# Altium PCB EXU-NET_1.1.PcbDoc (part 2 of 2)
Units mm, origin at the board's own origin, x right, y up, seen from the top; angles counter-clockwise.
Board outline 89 x 74.45 mm, 4 copper layers (Top Layer, Layer 1, Layer 2, Bottom Layer), stack 1.57 mm thick; 116 components, 84 nets, 406 pads, 488 vias.
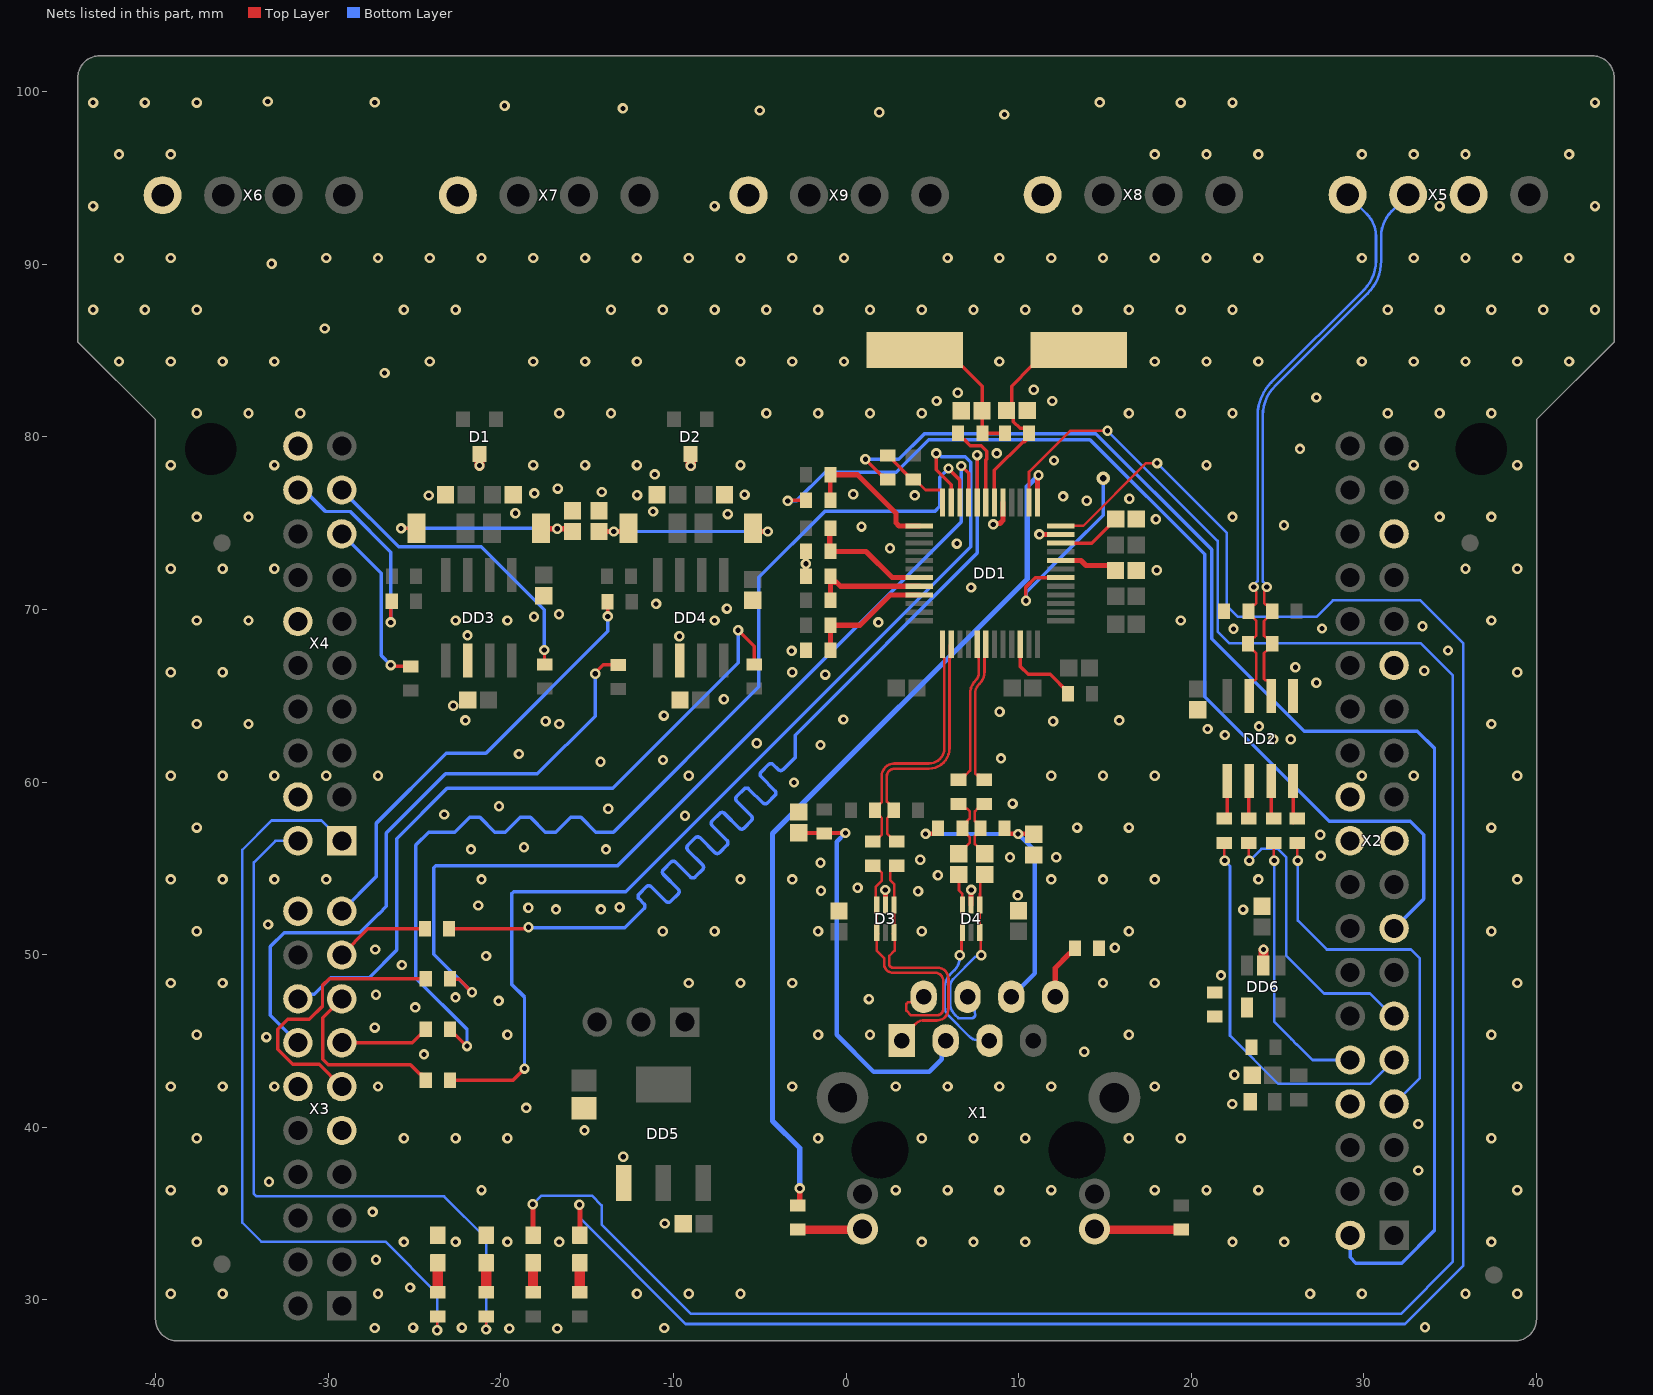
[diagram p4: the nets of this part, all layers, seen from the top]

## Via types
v1: diameter 0.6, hole 0.3, Top Layer to Bottom Layer, tented both sides, 487 vias
v2: diameter 0.8, hole 0.4, Top Layer to Bottom Layer, tented bottom, 1 vias

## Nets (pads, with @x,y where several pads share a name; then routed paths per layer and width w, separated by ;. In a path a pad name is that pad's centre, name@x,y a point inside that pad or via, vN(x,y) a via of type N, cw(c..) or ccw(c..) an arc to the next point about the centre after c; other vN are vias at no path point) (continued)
GND: C2.2 C3.2 C5.2 C6.2 C13.1 C14.1 C15.1 C16.1 C17.1 C18.2 C19.2 C20.2 C21.1 C22.1 C23.2 C24.2 C25.2 C26.1 C27.1 C28.1 C29.1 C30.2 C31.2 D1.3 D2.3 D3.2 D4.2 DD1.23 DD1.29 DD2.5 DD3.2 DD4.2 DD5.1 DD6.2 L1.2 R18.1 R20.1 R22.1 R32.1 R35.1 R54.2 VD3.2 VD4.2 X2.8 X2.19 X2.20 X2.22 X2.27 X2.33 X3.9 X3.12 X3.20 X4.4 X4.12 X4.20 X5.3 X6.1 X7.1 X8.1 X9.1 | length 7.1
  Top Layer w0.3: v1(2.27,53.745) 2.281,53.734 D3.2@2.281,52.887 ; D4.2@7.245,52.887 7.245,53.743 v1(7.259,53.757) ; v1(8.53,74.929) 8.587,74.986 8.913,74.986 9.099,75.172 DD1.29@9.099,76.193 ; v1(11.2,74.35) 11.207,74.343 DD1.23@12.449,74.343
  Top Layer w0.6: D1.3@-21.247,79.023 D1.3@-21.229,79.006 v1(-21.229,78.332) ; D2.3@-9.015,79.006 -8.997,78.989 v1(-8.997,78.315) ; C13.1@16.819,75.236 C13.1@16.863,75.281 ; DD6.2@24.172,49.383 24.185,49.395 v1(24.185,50.3)
  other v1: -19.5,28.35 -16.725,28.35 -27.3,28.375 -10.525,28.375 -25.075,28.4 -22.25,28.4 33.543,28.415 -39.113,30.363 -36.113,30.363 -27.113,30.363 -12.113,30.363 -9.113,30.363 -6.113,30.363 26.887,30.363 29.887,30.363 35.887,30.363 38.887,30.363 -25.25,30.725 -27.225,32.325 -37.613,33.363 -25.613,33.363 -22.613,33.363 -19.613,33.363 -16.613,33.363 4.387,33.363 7.387,33.363 10.387,33.363 22.387,33.363 25.387,33.363 37.387,33.363 -10.5,34.425 -27.425,35.1 -39.113,36.363 -36.113,36.363 -21.113,36.363 2.887,36.363 5.887,36.363 8.887,36.363 11.887,36.363 17.887,36.363 20.887,36.363 23.887,36.363 38.887,36.363 -33.425,36.85 33.15,37.5 -12.9,38.3 -37.613,39.363 -25.613,39.363 -22.613,39.363 -19.613,39.363 -1.613,39.363 4.387,39.363 7.387,39.363 10.387,39.363 16.387,39.363 19.387,39.363 37.387,39.363 -15.15,39.825 33.153,40.193 -18.525,41.125 22.375,41.35 -39.113,42.363 -36.113,42.363 -33.113,42.363 -27.113,42.363 -3.113,42.363 2.887,42.363 5.887,42.363 8.887,42.363 11.887,42.363 17.887,42.363 38.887,42.363 22.5,43.05 -24.45,44.225 13.8,44.375 -33.575,45.225 -37.613,45.363 -19.613,45.363 -1.613,45.363 1.387,45.363 16.387,45.363 37.387,45.363 -27.3,45.775 -24.95,46.95 -20.125,47.325 1.325,47.425 -22.625,47.525 -27.225,47.675 -39.113,48.363 -36.113,48.363 -9.113,48.363 -6.113,48.363 -3.113,48.363 14.887,48.363 17.887,48.363 38.887,48.363 21.721,48.8 -25.727,49.401 -20.85,49.925 -27.275,50.3 15.578,50.4 -37.613,51.363 -10.613,51.363 -7.613,51.363 -1.613,51.363 4.387,51.363 16.387,51.363 37.387,51.363 -33.475,51.75 23.006,52.612 -16.8,52.625 -14.2,52.625 -18.4,52.725 -13.112,52.759 -21.3,52.85 9.95,53.435 4.175,53.675 -1.45,53.7 0.675,53.875 -39.113,54.363 -36.113,54.363 -33.113,54.363 -30.113,54.363 -21.113,54.363 -6.113,54.363 -3.113,54.363 11.887,54.363 14.887,54.363 17.887,54.363 23.887,54.363 38.887,54.363 5.325,54.6 -1.475,55.325 4.3,55.5 9.5,55.65 12.175,55.65 27.5,55.725 -21.725,56.1 -13.9,56.1 -18.65,56.225 27.475,56.95 -37.613,57.363 13.387,57.363 16.387,57.363 37.387,57.363 -9.325,58.05 -23.275,58.125 -13.775,58.45 -20.1,58.6 9.65,58.75 -3.016,59.972 -39.113,60.363 -36.113,60.363 -33.113,60.363 -30.113,60.363 -27.113,60.363 -9.113,60.363 11.887,60.363 14.887,60.363 17.887,60.363 29.887,60.363 32.887,60.363 38.887,60.363 -14.225,61.175 -10.6,61.275 8.975,61.375 -18.95,61.625 -1.475,62.15 -5.175,62.25 24.75,62.475 25.765,62.484 21.95,62.725 20.95,63.075 23.925,63.225 -37.613,63.363 -34.613,63.363 -16.613,63.363 37.387,63.363 -17.4,63.525 12,63.525 -22.05,63.575 15.825,63.575 -0.15,63.625 -10.55,63.85 8.9,64.075 -22.75,64.425 -7.075,64.8 27.25,65.75 -1.2,66.225 -39.113,66.363 -36.113,66.363 -3.113,66.363 38.887,66.363 33.5,66.45 26.034,66.657 -3.15,67.6 34.875,67.625 -9.65,68.45 -21.925,68.5 22.45,68.875 27.575,68.9 33.4,69.025 1.875,69.25 -37.613,69.363 -34.613,69.363 -22.613,69.363 -19.613,69.363 -7.613,69.363 19.387,69.363 37.387,69.363 -18.075,69.575 -16.625,69.725 -6.9,70.05 -11,70.325 7.25,71.275 18,72.275 -39.113,72.363 -36.113,72.363 -33.113,72.363 35.887,72.363 38.887,72.363 -2.325,72.65 2.55,73.55 6.423,73.814 0.9,74.8 25.375,74.875 17.95,75.225 -37.613,75.363 -34.613,75.363 22.387,75.363 34.387,75.363 37.387,75.363 -6.85,75.525 -19.15,75.575 -11.175,75.675 13.95,76.3 16.419,76.417 12.575,76.55 -24.175,76.6 3.985,76.606 -12.1,76.625 -5.875,76.65 0.421,76.676 -18.05,76.725 -14.15,76.8 -16.7,77 -11.075,77.825 -39.113,78.363 -33.113,78.363 -18.113,78.363 -15.113,78.363 -12.113,78.363 -6.113,78.363 20.887,78.363 32.887,78.363 38.887,78.363 12.05,78.625 8.729,79.041 26.3,79.3 -37.613,81.363 -34.613,81.363 -31.613,81.363 -16.613,81.363 -13.613,81.363 -4.613,81.363 -1.613,81.363 1.387,81.363 4.387,81.363 16.387,81.363 19.387,81.363 22.387,81.363 31.387,81.363 34.387,81.363 37.387,81.363 5.25,82.075 11.95,82.075 27.25,82.275 6.475,82.55 10.875,82.725 -26.725,83.7 -42.113,84.363 -39.113,84.363 -36.113,84.363 -33.113,84.363 -24.113,84.363 -18.113,84.363 -15.113,84.363 -12.113,84.363 -6.113,84.363 -3.113,84.363 -0.113,84.363 8.887,84.363 17.887,84.363 20.887,84.363 23.887,84.363 29.887,84.363 32.887,84.363 35.887,84.363 38.887,84.363 41.887,84.363 -30.2,86.275 -43.613,87.363 -40.613,87.363 -37.613,87.363 -25.613,87.363 -22.613,87.363 -13.613,87.363 -10.613,87.363 -7.613,87.363 -4.613,87.363 -1.613,87.363 1.387,87.363 4.387,87.363 7.387,87.363 10.387,87.363 13.387,87.363 16.387,87.363 19.387,87.363 22.387,87.363 31.387,87.363 34.387,87.363 37.387,87.363 40.387,87.363 43.387,87.363 -33.275,90.025 -42.113,90.363 -39.113,90.363 -30.113,90.363 -27.113,90.363 -24.113,90.363 -21.113,90.363 -18.113,90.363 -15.113,90.363 -12.113,90.363 -9.113,90.363 -6.113,90.363 -3.113,90.363 -0.113,90.363 5.887,90.363 8.887,90.363 11.887,90.363 14.887,90.363 17.887,90.363 20.887,90.363 23.887,90.363 29.887,90.363 32.887,90.363 35.887,90.363 38.887,90.363 41.887,90.363 -43.613,93.363 -7.613,93.363 34.387,93.363 43.387,93.363 -42.113,96.363 -39.113,96.363 17.887,96.363 20.887,96.363 23.887,96.363 29.887,96.363 32.887,96.363 35.887,96.363 41.887,96.363 9.175,98.675 1.925,98.8 -5,98.9 -12.925,99.025 -19.775,99.175 -43.613,99.363 -40.613,99.363 -37.613,99.363 -27.3,99.375 14.7,99.375 19.387,99.363 22.387,99.363 43.387,99.363 -33.5,99.425
LINKLED: DD1.25 R11.2 | length 51
  Top Layer w0.3: R11.2@-2.782,35.476 -2.675,35.583 v1(-2.675,36.466) ; DD1.25@11.099,76.193 11.099,77.724 v1(11.149,77.774)
  Bottom Layer w0.3: v1(-2.675,36.466) -2.675,38.8 -4.25,40.375 -4.25,57.019 10.499,71.768 10.499,77.124 v1(11.149,77.774)
MISO: DD1.34 R26.1 | length 63.3
  Top Layer w0.2: R26.1@-22.945,45.674 -22.945,45.574 -22.695,45.324 -22.595,45.324 -21.976,44.705 v1(-21.956,44.705) ; v1(5.935,78.162) 6.599,77.499 DD1.34@6.599,76.193
  Bottom Layer w0.2: v1(-21.956,44.705) -21.956,45.674 -24.919,48.637 -24.919,56.356 -24.177,57.098 -23.067,57.098 -22.667,57.098 -21.804,57.961 -21.204,57.961 -20.341,57.098 -19.741,57.098 -18.878,57.961 -18.278,57.961 -17.415,57.098 -16.815,57.098 -15.952,57.961 -15.352,57.961 -14.489,57.098 -13.95,57.098 -13.469,57.098 -5.05,65.517 -5.05,71.868 -1.242,75.677 5.135,75.677 5.425,75.967 5.425,77.652 v1(5.935,78.162)
MOSI: DD1.35 R27.1 | length 60.3
  Top Layer w0.2: R27.1@-22.945,42.74 -19.287,42.74 v1(-18.624,43.403) ; v1(5.23,79.042) 5.23,78.089 6.099,77.221 DD1.35@6.099,76.193
  Bottom Layer w0.2: v1(-18.624,43.403) -18.624,47.549 -19.375,48.3 -19.375,53.526 -19.258,53.643 -12.754,53.643 7.226,73.623 7.226,78.534 7.093,78.668 6.904,78.856 5.524,78.856 5.339,79.042 v1(5.23,79.042)
NetC5_1: C5.1 R13.2 R14.2 Y1.2 | length 8.9
  Top Layer w0.2: Y1.2@3.987,85.033 4.937,84.083 6.737,84.083 7.881,82.938 C5.1@7.881,81.387 ; R13.2@7.881,80.187 R13.2@7.998,80.071 ; R13.2@7.881,80.312 C5.1@7.881,81.512 ; R13.2@7.998,80.196 R14.2@9.212,80.196
NetC13_2: C13.2 DD1.22 | length 3.7
  Top Layer w0.2: DD1.22@12.449,73.843 14.225,73.843 C13.2@15.619,75.236
NetC14_2: C14.2 DD1.20 | length 3.4
  Top Layer w0.3: DD1.20@12.449,72.843 13.607,72.843 13.9,72.55 15.321,72.55 C14.2@15.617,72.254
NetC20_1: C20.1 R37.2 R38.2 | length 12
  Top Layer w0.2: v1(-25.771,74.698) -24.896,74.698 R37.2@-24.887,74.707 ; R38.2@-17.662,74.707 R38.2@-17.634,74.679 ; C20.1@-16.003,74.679 C20.1@-15.837,74.514 ; C20.1@-15.914,74.137 C20.1@-15.837,74.213
  Top Layer w0.3: R38.2@-17.634,74.679 C20.1@-16.003,74.679
  Bottom Layer w0.2: v1(-25.771,74.698) -16.747,74.698 v1(-16.728,74.679)
NetC25_1: C25.1 R40.2 R41.2 | length 11.5
  Top Layer w0.15: v1(-4.531,74.519) v1@-4.525,74.525
  Top Layer w0.3: C25.1@-14.304,74.514 v1(-13.456,74.514) -12.608,74.514 R40.2@-12.602,74.519 ; R41.2@-5.394,74.519 v1(-4.531,74.519)
  Bottom Layer w0.15: v1(-13.456,74.514) -4.531,74.514 v1(-4.531,74.519)
NetDD1_10: DD1.10 R15.2 | length 4.8
  Top Layer w0.2: DD1.10@10.104,67.988 10.104,66.693 10.557,66.24 11.834,66.24 12.861,65.213 R15.2@12.861,65.113
NetDD1_24: DD1.24 VD2.2 | length 126.1
  Top Layer w0.15: DD1.24@12.449,74.843 13.743,74.843 17.375,78.475 v1(18.025,78.475)
  Top Layer w0.3: v1(-15.443,35.517) -15.415,35.489 VD2.2@-15.415,33.75
  Bottom Layer w0.15: v1(-15.443,35.517) -15.443,34.769 -9.284,28.61 32.385,28.61 35.75,31.975 35.75,68.05 33.275,70.525 28.2,70.525 27.25,69.575 22.7,69.575 22.05,70.225 22.05,74.45 v1(18.025,78.475)
NetDD1_26: DD1.26 VD1.2 | length 130.3
  Top Layer w0.15: DD1.26@10.599,76.193 10.599,77.967 12.982,80.35 v1(15.15,80.35)
  Top Layer w0.3: v1(-18.147,35.544) -18.129,35.526 VD1.2@-18.129,33.75
  Bottom Layer w0.15: v1(-18.147,35.544) -18.129,35.544 -17.631,36.042 -14.719,36.042 -14.15,35.473 -14.15,34.363 -8.987,29.2 32.14,29.2 35.16,32.22 35.16,66.171 33.28,68.05 22.191,68.05 21.53,68.711 21.53,73.97 v1(15.15,80.35)
NetDD1_36: DD1.36 R12.1 R53.1 | length 4.8
  Top Layer w0.15: R12.1@3.905,77.517 4.005,77.517 4.604,76.918 5.524,76.918 5.599,76.843 DD1.36@5.599,76.193
  Top Layer w0.2: R53.1@2.414,78.927 2.514,78.927 2.764,78.677 2.764,78.577 3.555,77.786 3.555,77.767 3.805,77.517 R12.1@3.905,77.517
NetDD6_4: DD6.4 R31.1 R32.2
NetR9_1: R9.1 X1.10 | length 5
  Top Layer w0.5: X1.10@14.4,34.105 14.429,34.076 R9.1@19.415,34.076
NetR11_1: R11.1 X1.12 | length 3.7
  Top Layer w0.15: X1.12@0.921,34.076 X1.12@0.95,34.105
  Top Layer w0.5: R11.1@-2.782,34.076 X1.12@0.921,34.076
NetR16_2: R16.2 VD1.1 | length 1.7
  Top Layer w0.6: R16.2@-18.129,30.444 VD1.1@-18.129,32.103
NetR17_2: R17.2 VD2.1 | length 1.7
  Top Layer w0.6: R17.2@-15.415,30.444 VD2.1@-15.415,32.103
NetR29_1: R29.1 VD3.1 | length 1.7
  Top Layer w0.6: R29.1@-23.645,30.444 VD3.1@-23.645,32.103
NetR30_1: R30.1 VD4.1 | length 1.7
  Top Layer w0.6: R30.1@-20.85,30.444 VD4.1@-20.85,32.103
NetR53_2: R53.2 X2.2 | length 80.9
  Top Layer w0.2: v1(1.125,78.7) 2.048,77.777 2.164,77.777 R53.2@2.414,77.527
  Bottom Layer w0.2: v1(1.125,78.7) 3.062,78.7 4.546,80.184 14.47,80.184 21.183,73.471 21.183,68.306 26.538,62.95 33.1,62.95 34.09,61.96 34.09,34.027 32.2,32.137 29.54,32.137 29.21,32.467 X2.2@29.21,33.74
NetR54_1: R54.1 X1.8 | length 3.3
  Top Layer w0.3: X1.8@12.12,47.565 12.12,49.235 12.954,50.069 13.054,50.069 13.254,50.269 R54.1@13.254,50.369
PA8: R28.2 X3.17 | length 5.4
  Top Layer w0.2: X3.17@-29.21,49.98 -27.693,51.497 R28.2@-24.395,51.497
PA9: R25.2 X3.11 | length 16.3
  Top Layer w0.2: X3.11@-29.21,42.36 -29.23,42.36 -30.52,43.65 -32.056,43.65 -32.925,44.519 -32.925,45.675 -32.35,46.25 -31.1,46.25 -30.325,47.025 -30.325,48.225 -29.945,48.605 R25.2@-24.345,48.605
PA10: R27.2 X3.15 | length 10.5
  Top Layer w0.2: X3.15@-29.21,47.44 -30.31,46.34 -30.31,43.935 -30,43.625 -25.23,43.625 -24.695,43.09 -24.595,43.09 -24.345,42.84 R27.2@-24.345,42.74
PA11: R26.2 X3.13 | length 5.2
  Top Layer w0.2: X3.13@-29.21,44.9 -25.119,44.9 R26.2@-24.345,45.674
PA13: R48.2 X3.19 | length 25.7
  Top Layer w0.2: R48.2@-13.813,70.449 -13.813,69.613 v1(-13.8,69.6)
  Bottom Layer w0.2: X3.19@-29.21,52.52 -27.225,54.505 -27.225,57.6 -23.15,61.675 -20.854,61.675 -13.8,68.729 v1(-13.8,69.6)
PA14: R46.2 X3.14 | length 37.1
  Top Layer w0.2: v1(-14.521,66.279) -14.521,66.329 -14.063,66.787 R46.2@-13.191,66.787
  Bottom Layer w0.2: X3.14@-31.75,44.9 -33.35,46.5 -33.35,50.475 -32.55,51.275 -28.175,51.275 -27.075,52.375 -27.05,52.375 -26.625,52.8 -26.625,57.05 -23.2,60.475 -17.875,60.475 -14.525,63.825 -14.525,66.275 v1(-14.521,66.279)
PA15: R47.2 X3.16 | length 41.6
  Top Layer w0.2: v1(-6.25,68.8) -5.319,67.869 R47.2@-5.319,66.82
  Bottom Layer w0.2: X3.16@-31.75,47.44 -31.469,47.721 -30.804,47.721 -29.85,48.675 -27.625,48.675 -26.025,50.275 -26.025,56.725 -23.112,59.638 -13.523,59.638 -6.25,66.911 v1(-6.25,68.8)
PB0: R29.2 X4.1 | length 44.5
  Top Layer w0.15: v1(-23.684,28.249) -23.684,29.005 R29.2@-23.645,29.044
  Bottom Layer w0.15: X4.1@-29.21,56.6 -30.385,57.775 -33.275,57.775 -34.975,56.075 -34.975,34.475 -33.874,33.374 -26.674,33.374 -23.684,30.384 v1(-23.684,28.249)
PB1: R30.2 X4.2 | length 42.9
  Top Layer w0.15: v1(-20.85,28.288) R30.2@-20.85,29.044 R30.2@-20.811,29.083
  Bottom Layer w0.15: X4.2@-31.75,56.6 -33.05,56.6 -34.3,55.35 -34.3,36.15 -34.15,36 -23.275,36 -20.85,33.575 v1(-20.85,28.288)
PB6: R49.2 X4.15 | length 10
  Top Layer w0.2: v1(-26.375,66.775) -26.302,66.702 R49.2@-25.208,66.702
  Bottom Layer w0.2: X4.15@-29.21,74.38 -26.932,72.102 -26.932,67.332 v1(-26.375,66.775)
PB7: R50.2 X4.17 | length 17.8
  Top Layer w0.2: v1(-17.475,67.65) -17.464,67.65 R50.2@-17.464,66.82
  Bottom Layer w0.2: X4.17@-29.21,76.92 -25.915,73.625 -21.125,73.625 -17.475,69.975 v1(-17.475,67.65)
PB11: R51.2 X4.18 | length 12.2
  Top Layer w0.2: v1(-26.375,69.25) -26.375,70.408 R51.2@-26.313,70.47
  Bottom Layer w0.2: X4.18@-31.75,76.92 -31.395,76.92 -30.15,75.675 -28.725,75.675 -26.375,73.325 v1(-26.375,69.25)
PC6: R42.1 X2.7 | length 21.4
  Top Layer w0.15: v1@26.146,55.475 R42.1@26.146,56.429
  Bottom Layer w0.15: v1(26.172,55.45) 26.172,51.978 27.85,50.3 32.725,50.3 32.775,50.25 33.225,49.8 33.225,42.835 X2.7@31.75,41.36
PC7: R43.1 X2.9 | length 22.5
  Top Layer w0.15: v1@21.915,55.475 R43.1@21.915,56.429
  Bottom Layer w0.15: v1(21.941,55.45) 21.941,55.442 22.246,55.137 22.246,45.308 25.04,42.514 30.364,42.514 X2.9@31.75,43.9
PC8: R44.1 X2.10 | length 15.6
  Top Layer w0.15: v1@24.78,55.475 R44.1@24.78,56.429
  Bottom Layer w0.15: v1(24.806,55.45) 24.806,46.118 25.795,45.129 25.795,45.105 26.103,44.797 26.127,44.797 27.024,43.9 X2.10@29.21,43.9
PC9: R45.1 X2.11 | length 17
  Top Layer w0.15: v1@23.338,55.475 R45.1@23.338,56.429
  Bottom Layer w0.15: v1@23.373,55.44 24.061,56.128 25.022,56.128 25.5,55.65 25.5,49.95 27.7,47.75 30.35,47.75 31.66,46.44 X2.11@31.75,46.44
  other v1: 23.364,55.45
PC11: R52.1 X2.15 | length 59.7
  Top Layer w0.2: v1(-3.373,76.288) -3.348,76.313 R52.1@-2.373,76.313
  Bottom Layer w0.2: v1(-3.373,76.288) -2.866,76.288 -1.204,77.95 2.908,77.95 4.792,79.834 14.133,79.834 20.775,73.191 20.775,64.95 27.998,57.727 28.743,57.727 32.217,57.727 32.675,57.727 33.457,56.944 33.457,53.227 X2.15@31.75,51.52
PMODE0: DD1.45 R22.2 R23.1 | length 7.3
  Top Layer w0.3: R22.2@-0.906,67.643 R23.1@-0.906,69.088 0.813,69.088 2.568,70.843 DD1.45@4.249,70.843
PMODE1: DD1.44 R20.2 R21.1 | length 6.7
  Top Layer w0.3: R21.1@-0.906,70.534 -0.906,71.828 -0.656,71.578 -0.556,71.578 -0.321,71.343 DD1.44@4.249,71.343
PMODE2: DD1.43 R18.2 R19.1 | length 7.2
  Top Layer w0.3: R19.1@-0.906,74.707 -0.942,74.671 -0.942,73.359 1.166,73.359 2.682,71.843 DD1.43@4.249,71.843
RCT: C3.1 R7.1 R8.2 X1.6 | length 18.2
  Top Layer w0.254: v1(4.613,57) 5.309,57 R8.2@5.34,57.031 ; R7.1@9.192,57.015 10.84,57.015 C3.1@10.873,56.981
  Bottom Layer w0.254: v1(4.613,57) 4.624,56.99 v1(9.972,56.99) 10.945,56.017 10.945,48.93 X1.6@9.58,47.565
RS485_N: DD2.7 R34.1 R35.2 X5.1 | length 33.2
  Top Layer w0.15: DD2.7@23.356,64.978 23.356,65.684 23.56,65.888 23.678,65.888 23.766,65.976 23.766,66.15 23.766,67.458 23.574,67.65 23.566,67.65 23.291,67.925 R34.1@23.291,68.025 23.291,68.125 23.566,68.4 23.678,68.4 23.766,68.488 23.766,69.345 23.307,69.804 R35.2@23.307,69.904 23.307,70.004 23.582,70.279 23.686,70.279 23.774,70.367 23.774,71.028
  Bottom Layer w0.15: v1(23.624,71.3) 23.624,71.422 23.843,71.641 23.843,81.241 cw(c26.533,81.241) 24.631,83.143 29.999,88.511 ccw(c28.31,90.202) 30.7,90.202 30.7,91.625 ccw(c28.876,91.625) 30.166,92.914 X5.1@29.057,94.023
RS485_P: DD2.6 R33.1 R34.2 X5.2 | length 33.5
  Top Layer w0.15: v1(24.374,71.3) 24.374,71.178 24.224,71.028 24.224,70.367 24.312,70.279 24.416,70.279 24.691,70.004 R33.1@24.691,69.904 24.691,69.804 24.216,69.329 24.216,68.488 24.304,68.4 24.416,68.4 24.691,68.125 R34.2@24.691,68.025 24.691,67.925 24.416,67.65 24.403,67.65 24.216,67.464 24.216,66.337 24.216,65.976 24.304,65.888 24.422,65.888 24.626,65.684 DD2.6@24.626,64.978
  Bottom Layer w0.15: v1(24.374,71.3) 24.374,71.382 24.143,71.613 24.143,81.241 cw(c26.533,81.241) 24.844,82.932 30.212,88.3 ccw(c28.31,90.202) 31,90.202 31,91.625 cw(c33.019,91.625) 31.591,93.052 X5.2@32.562,94.023
RSTn: DD1.37 R24.2 R52.2 | length 8.2
  Top Layer w0.254: R52.2@-0.906,76.313 R24.2@-0.906,77.803
  Top Layer w0.3: R24.2@-0.906,77.803 0.674,77.803 2.9,75.577 2.9,75.019 3.076,74.843 DD1.37@4.249,74.843
RX0_N: C4.2 D4.3 D4.4 X1.5 | length 12
  Top Layer w0.15: C4.2@6.529,54.643 6.544,54.628 6.544,53.729 6.745,53.528 D4.3@6.745,52.887 D4.4@6.745,51.277 6.691,51.223 6.691,50.195 6.588,50.092 v1(6.588,49.97)
  Bottom Layer w0.15: 5.941,46.467 cw(c6.465,46.99) 5.725,46.99 5.725,48.149 cw(c6.679,48.149) 6.004,48.824 6.296,49.115 ccw(c5.592,49.819) 6.588,49.819 v1(6.588,49.97) ; 5.942,46.467 7.139,45.269 ccw(c7.729,45.859) 7.729,45.025 X1.5@8.31,45.025 X1.5@8.05,45.285
RX0_P: C1.2 D4.1 D4.6 X1.4 | length 12.3
  Top Layer w0.15: v1(7.832,49.97) 7.813,49.989 7.813,51.21 D4.6@7.745,51.277 D4.1@7.745,52.887 7.764,52.907 7.764,53.52 7.784,53.539 7.784,54.396 C1.2@8.031,54.643
  Bottom Layer w0.15: X1.4@7.04,47.04 X1.4@7.04,47.565 cw(c5.982,46.507) 7.478,46.507 cw(c7.296,46.507) 7.296,46.325 6.508,46.325 6.318,46.515 cw(c7.026,47.223) 6.025,47.223 6.025,48.134 cw(c6.668,48.134) 6.213,48.588 7.508,49.883 7.745,49.883 v1(7.832,49.97)
RX1_N: C4.1 R8.1 R10.2 | length 3.9
  Top Layer w0.15: R10.2@6.518,58.736 6.793,58.461 7.011,58.461 7.161,58.312 7.161,57.884 7.015,57.738 7.015,57.606 R8.1@6.74,57.331 6.74,57.231 7.161,56.811 7.161,56.475 C4.1@6.529,55.843
RX1_P: C1.1 R4.2 R7.2 | length 3.7
  Top Layer w0.15: R4.2@8.006,58.736 7.731,58.461 7.627,58.461 7.461,58.295 7.461,57.746 7.792,57.415 R7.2@7.792,57.315 7.792,57.215 7.461,56.884 7.461,56.414 C1.1@8.031,55.843
RX_N: DD1.5 R10.1 | length 8.4
  Top Layer w0.15: R10.1@6.518,60.136 6.793,60.411 6.937,60.411 7.187,60.661 7.187,65.105 cw(c8.32,65.105) 7.519,65.906 ccw(c7.028,66.397) 7.7,66.221 7.7,67.18 7.674,67.206 7.674,67.918 DD1.5@7.599,67.993
RX_P: DD1.6 R4.1 | length 8.3
  Top Layer w0.15: R4.1@8.006,60.136 7.731,60.411 7.575,60.411 7.487,60.499 7.487,65.105 cw(c8.32,65.105) 7.731,65.694 ccw(c7.028,66.397) 8.022,66.397 8.022,67.18 8.024,67.182 8.024,67.918 DD1.6@8.099,67.993
SCLK: DD1.33 R25.1 | length 54.1
  Top Layer w0.2: R25.1@-22.945,48.605 -22.915,48.575 -22.412,48.575 v1(-21.664,47.827) ; v1(6.676,78.306) 6.676,78.303 7.099,77.88 DD1.33@7.099,76.193
  Bottom Layer w0.2: v1(-21.664,47.827) -23.875,50.038 -23.875,55.04 -23.758,55.157 -13.234,55.157 6.676,75.068 v1(6.676,78.306)
SCS: DD1.32 R28.1 | length 64.2
  Top Layer w0.2: R28.1@-22.995,51.497 -18.586,51.497 -18.497,51.585 v1(-18.389,51.585) ; v1(7.597,78.941) 7.599,78.94 DD1.32@7.599,76.193
  Bottom Layer w0.2: v1(-18.389,51.585) -18.353,51.55 -12.821,51.55 -11.775,52.596 -11.705,52.667 ccw(c-11.846,52.808) -11.705,52.95 -11.988,53.232 cw(c-11.846,53.374) -11.988,53.515 -11.563,53.94 cw(c-11.422,53.798) -11.28,53.94 -10.432,53.091 ccw(c-10.29,53.232) -10.149,53.091 -9.725,53.515 ccw(c-9.866,53.657) -9.725,53.798 -10.573,54.647 cw(c-10.432,54.788) -10.573,54.929 -10.149,55.354 cw(c-10.008,55.212) -9.866,55.354 -9.018,54.505 ccw(c-8.876,54.647) -8.735,54.505 -8.311,54.929 ccw(c-8.452,55.071) -8.311,55.212 -9.159,56.061 cw(c-9.018,56.202) -9.159,56.344 -8.735,56.768 cw(c-8.593,56.627) -8.452,56.768 -7.603,55.919 ccw(c-7.462,56.061) -7.321,55.919 -6.896,56.344 ccw(c-7.038,56.485) -6.896,56.627 -7.745,57.475 cw(c-7.603,57.616) -7.745,57.758 -7.321,58.182 cw(c-7.179,58.041) -7.038,58.182 -6.191,57.336 ccw(c-6.05,57.477) -5.908,57.336 -5.484,57.76 ccw(c-5.626,57.901) -5.484,58.043 -6.331,58.889 cw(c-6.189,59.031) -6.331,59.172 -5.906,59.596 cw(c-5.765,59.455) -5.624,59.596 -4.825,58.798 ccw(c-4.684,58.94) -4.543,58.798 -4.118,59.222 ccw(c-4.26,59.364) -4.118,59.505 -4.916,60.303 cw(c-4.775,60.445) -4.916,60.586 -4.492,61.011 cw(c-4.351,60.869) -4.209,61.011 -3.927,60.728 ccw(c-3.785,60.869) -3.644,60.728 -2.95,61.422 -2.95,62.723 7.597,73.27 v1(7.597,78.941)
TCT: C2.1 R3.1 X1.3 | length 23.1
  Top Layer w0.254: C2.1@-2.742,57.067 -2.728,57.053 R3.1@-1.26,57.053 ; R3.1@-1.271,57.053 v1(-0.036,57.053)
  Bottom Layer w0.254: v1(-0.036,57.053) -0.541,56.548 -0.541,45.366 1.6,43.225 4.825,43.225 5.549,43.949 5.549,44.804 X1.3@5.77,45.025
TP1: DD1.18 | length 12
  Top Layer w0.2: v1(10.425,70.5) 10.425,71.3 10.968,71.843 DD1.18@12.449,71.843
  Bottom Layer w0.2: v1(10.425,70.5) 10.436,70.511 10.436,70.991 13.094,73.65 14.9,75.456 v2(14.9,77.6)
TX0_N: D3.3 D3.4 R6.1 X1.2 | length 16.1
  Top Layer w0.15: R6.1@1.559,55.154 1.659,55.154 2.082,54.731 2.082,54.3 1.73,53.948 1.73,53.386 ; D3.4@1.771,51.267 1.771,50.238 2.206,49.802 2.206,49.469 ccw(c2.725,49.469) 2.725,48.95 5.172,48.95 cw(c5.172,48.485) 5.637,48.485 5.637,46.865 cw(c5.262,46.865) 5.262,46.491 3.776,46.491 3.5,46.767 3.5,47.15 3.6,47.25 4.185,47.25 X1.2@4.5,47.565 X1.2@4.5,47.005 ; D3.3@1.781,52.887 D3.4@1.781,51.277 D3.4@1.856,51.202
TX0_P: D3.1 D3.6 R5.1 X1.1 | length 15.5
  Top Layer w0.15: D3.6@2.708,51.204 D3.6@2.781,51.277 D3.1@2.781,52.887 2.799,52.906 2.799,54.079 2.556,54.323 2.556,54.879 2.831,55.154 R5.1@2.931,55.154 ; D3.6@2.821,51.238 2.821,50.238 2.506,49.923 2.506,49.469 ccw(c2.725,49.469) 2.725,49.25 5.296,49.25 cw(c5.296,48.609) 5.937,48.609 5.937,46.865 cw(c5.262,46.865) 5.262,46.191 4.432,46.191 ccw(c4.552,45.415) 3.997,45.97 3.927,45.9 3.917,45.9 3.23,45.212 X1.1@3.23,45.025
TX_N: DD1.1 R2.1 R6.2 | length 15
  Top Layer w0.15: R6.2@1.559,56.554 1.659,56.554 2.081,56.976 2.081,57.905 1.993,57.992 1.959,57.992 1.684,58.267 R2.1@1.684,58.367 1.684,58.467 2.072,58.856 2.072,60.347 cw(c2.8,60.347) 2.8,61.075 4.8,61.075 ccw(c4.8,61.972) 5.697,61.972 5.697,67.18 5.674,67.203 5.674,67.268 5.599,67.343 DD1.1@5.599,67.993
TX_P: DD1.2 R1.1 R5.2 | length 15
  Top Layer w0.15: R5.2@2.931,56.554 2.831,56.554 2.556,56.829 2.556,56.834 2.381,57.009 2.381,57.905 2.468,57.992 2.492,57.992 2.767,58.267 R1.1@2.767,58.367 2.767,58.467 2.372,58.862 2.372,60.347 cw(c2.8,60.347) 2.8,60.775 4.8,60.775 ccw(c4.8,61.972) 5.997,61.972 5.997,67.18 6.024,67.207 6.024,67.918 DD1.2@6.099,67.993
UART6_DE/PC8: DD2.3 R44.2 | length 2.2
  Top Layer w0.2: DD2.3@24.626,60.051 24.626,58.033 R44.2@24.78,57.879
UART6_RE/PC9: DD2.2 R45.2 | length 2.2
  Top Layer w0.2: R45.2@23.338,57.879 23.338,60.033 DD2.2@23.356,60.051
UART6_RX/PC7: DD2.1 R43.2 | length 2.2
  Top Layer w0.2: R43.2@21.915,57.879 22.085,58.049 DD2.1@22.086,60.051
UART6_TX/PC6: DD2.4 R42.2 | length 2.4
  Top Layer w0.2: R42.2@25.896,57.654 DD2.4@25.896,60.051
XI: C6.1 DD1.30 R14.1 Y1.1 | length 13.1
  Top Layer w0.2: DD1.30@8.599,76.193 8.599,78.058 10.262,79.721 10.362,79.721 10.612,79.971 10.612,80.243 10.362,80.493 10.085,80.493 9.7,80.878 9.7,81.052 9.425,81.327 C6.1@9.3,81.327 ; C6.1@9.593,81.387 9.593,82.938 10.738,84.083 12.537,84.083 Y1.1@13.487,85.033
XO: DD1.31 R13.1 | length 5.1
  Top Layer w0.2: R13.1@6.498,80.196 6.498,80.096 6.748,79.846 6.848,79.846 7.203,79.49 7.369,79.49 ; 7.37,79.491 7.825,79.491 8.147,79.169 8.147,78.713 8.099,78.665 DD1.31@8.099,76.193
pads on no net: DD1.7 DD1.12 DD1.13 DD1.38 DD1.39 DD1.40 DD1.41 DD1.42 DD1.46 DD1.47 FM4.1 FM5.1 FM6.1 FM7.1 X1.7 X1.DNC X1.MH X2.1 X2.3 X2.4 X2.5 X2.6 X2.12 X2.13 X2.14 X2.16 X2.17 X2.21 X2.23 X2.24 X2.25 X2.26 X2.28 X2.29 X2.30 X2.31 X2.32 X2.34 X2.35 X2.36 X2.37 X2.38 X3.1 X3.2 X3.3 X3.4 X3.5 X3.6 X3.7 X3.8 X3.10 X3.18 X4.3 X4.5 X4.6 X4.7 X4.8 X4.9 X4.10 X4.11 X4.13 X4.14 X4.16 X4.19

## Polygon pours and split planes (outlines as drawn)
3V3 on Layer 1 "3V3_L02_P034" (solid, pour order 34): -43.23,102.072 43.23,102.072 cw(c43.23,100.802) 44.5,100.802 44.5,85.5 40,81 40,28.895 cw(c38.73,28.895) 38.73,27.625 -38.73,27.625 cw(c-38.73,28.895) -40,28.895 -40,81 -44.5,85.5 -44.5,100.802 cw(c-43.23,100.802)
5V on Layer 1 "Layer 1-5V" (solid, pour order 16): 24.782,54.568 26.625,52.725 29.975,52.725 30.35,53.1 30.35,54.9 29.95,55.3 28.55,55.3 27.875,55.975 27.875,80.6 27.95,80.675 27.875,80.75 27.875,96.975 28.7,97.8 36.653,97.8 38.05,96.403 38.05,92.425 41.225,92.425 41.225,98.8 39.575,100.45 26.75,100.45 24.782,98.482
12V on Layer 1 "Layer 1-12V" (solid, pour order 30): -37.775,90.15 -27.55,79.925 -27.55,62.175 -24.975,59.6 -18.875,59.6 -17.675,58.4 -17.675,38 -12.375,32.7 -7.7,32.7 -6.925,33.475 -6.925,36.975 -7.275,37.325 -13.075,37.325 -15.675,39.925 -15.675,47.8 -14.65,48.825 -14.65,60.2 -16.55,62.1 -22.05,62.1 -23.35,63.4 -23.35,71.775 -24.48,72.905 -24.48,82.505 -34.375,92.4 -34.375,96.175 -21.45,96.175 -20.85,95.575 -20.85,93.05 -20.125,92.325 -17.675,92.325 -17.325,92.675 -17.325,95.375 -16.5,96.2 -4.7,96.2 -3.925,95.425 -3.925,92.275 -1.025,92.275 -0.525,92.775 -0.525,95.275 0.375,96.175 12.325,96.175 13.175,95.325 13.175,92.8 13.825,92.15 15.9,92.15 16.7,92.95 16.7,98.7 15.425,99.975 -35.65,99.975 -37.775,97.85 -37.775,96.2
AGND on Layer 2 "Layer 2-AGND" (solid, pour order 8): 7.9,64.2 17.825,64.2 18.9,63.125 18.9,41.598 22.306,38.192 26.005,38.192 26.72,38.908 26.72,43.196 24.954,43.196 21.55,46.6 21.55,63.6 18.35,66.8 18.35,70.425 18.375,70.425 18.375,70.925 18.175,71.125 16.85,71.125 16.525,71.45 16.525,73.1 16.775,73.35 18.194,73.35 18.375,73.531 18.375,74.12 18.17,74.325 14.55,74.325 13.75,73.525 8.641,73.525 1.775,66.659 1.775,65.4 -0.15,63.475 -0.15,60.959 -1.766,59.344 -1.766,57.65 7.35,57.65 7.35,63.65
GND on Layer 2 "GND_L03_P032" (solid, pour order 32): -43.23,102.072 43.23,102.072 cw(c43.23,100.802) 44.5,100.802 44.5,85.5 40,81 40,28.895 cw(c38.73,28.895) 38.73,27.625 -38.73,27.625 cw(c-38.73,28.895) -40,28.895 -40,81 -44.5,85.5 -44.5,100.802 cw(c-43.23,100.802)
GND on Layer 2 "GND_L03_P031" (solid, pour order 31): -43.23,102.072 43.23,102.072 cw(c43.23,100.802) 44.5,100.802 44.5,85.5 40,81 40,28.895 cw(c38.73,28.895) 38.73,27.625 -38.73,27.625 cw(c-38.73,28.895) -40,28.895 -40,81 -44.5,85.5 -44.5,100.802 cw(c-43.23,100.802)
3V3A on Bottom Layer "Bottom Layer-3V3A" (solid, pour order 6): 17.825,61.75 18.925,60.65 18.925,41.665 22.265,38.326 25.627,38.326 26.72,39.419 26.72,40.675 25.234,40.675 21.375,44.534 21.375,61.3 18.35,64.325 18.35,68.4 18.375,68.425 18.175,68.625 16.85,68.625 16.525,68.95 16.525,70.6 16.775,70.85 18.194,70.85 18.375,71.031 18.375,71.62 16.267,73.728 14.444,73.728 11.641,70.924 9.354,70.924 2.271,63.842 2.271,63.34 -1.617,59.452 -1.617,57.964 7,57.964 7,61.05 7.7,61.75
GND on Bottom Layer "GND_L04_P033" (solid, pour order 33): -43.23,102.072 43.23,102.072 cw(c43.23,100.802) 44.5,100.802 44.5,85.5 40,81 40,28.895 cw(c38.73,28.895) 38.73,27.625 -38.73,27.625 cw(c-38.73,28.895) -40,28.895 -40,81 -44.5,85.5 -44.5,100.802 cw(c-43.23,100.802)
GND on Top Layer "GND_L01_P023" (solid, pour order 23): -43.23,102.072 43.23,102.072 cw(c43.23,100.802) 44.5,100.802 44.5,85.5 40,81 40,28.895 cw(c38.73,28.895) 38.73,27.625 -38.73,27.625 cw(c-38.73,28.895) -40,28.895 -40,81 -44.5,85.5 -44.5,100.802 cw(c-43.23,100.802)

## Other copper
Top Layer:
  pour cut-out: -0.256,66.893 -0.256,65.281 1.55,63.475 5.325,63.475 5.325,66.851 5.149,67.027
  pour cut-out: 2.163,43.769 11.546,43.769 13.151,45.375 13.151,48.024 12.5,48.675 3.226,48.675 2.163,47.612 2.163,46.269
  region net 3V3A: 0.634,57.917 -1.571,57.917 -1.721,58.067 -1.721,59.295 -1.516,59.499 0.359,59.499 0.634,59.224 0.634,58.817
  pour cut-out: 5.768,60.486 6.627,60.486 6.984,60.843 6.984,65.804 6.636,66.153 6.437,66.153 6.35,66.065 6.35,61.33 5.678,60.659
  pour cut-out: 2.8,60.393 3.016,60.608 5.645,60.608 5.768,60.486 5.768,57.786 5.306,57.786 5.301,57.781 4.091,57.781 2.755,59.117
  pour cut-out: 0.809,54.504 0.809,58.992 0.934,59.117 4.817,59.117 4.817,57.617 4.094,57.617 3.681,57.204 3.681,54.504
  pour cut-out: 10.209,80.946 14.47,80.946 14.684,80.732 13.905,80.732 11.851,78.678 10.769,78.678 10.769,78.816 10.352,79.234
  pour cut-out: 4.249,69.343 4.249,74.843 5.599,76.193 11.099,76.193 12.449,74.843 12.449,69.343 11.099,67.993 5.599,67.993
  pour cut-out: 3.359,76.867 4.818,76.867 5.149,76.536 5.149,75.293 3.368,75.293 3.359,75.302
  pour cut-out: -25.653,72.683 -25.712,72.742 -25.712,75.857 -20.287,75.857 -19.109,74.679 -17.437,74.679 -16.837,75.279 -10.324,75.279 -9.752,74.707 -5.067,74.707 -4.222,73.863 -4.222,73.507 -5.405,72.325 -24.186,72.325 -24.253,72.392
  region net 3V3: 22.365,63.993 21.807,63.993 20.908,64.892 19.859,64.892 18.802,65.949 18.802,66.628 18.971,66.797 21.531,66.797 22.365,65.963
  region net 12V: -8.725,37.825 -7.825,37.825 -6.95,36.95 -6.95,33.45 -7.7,32.7 -8.575,32.7 -8.725,32.85 -8.725,34.911
  region net 5V_EXT: -10.125,37.9 -8.775,39.25 -8.775,43.325 -8.975,43.525 -11.925,43.525 -13.2,44.8 -13.2,47.7 -15.892,47.7 -15.892,42.062 -14.442,42.062 -11.58,39.2 -11.58,35.725 -10.125,35.725
  region net 3V3: -19.648,70.999 -19.648,73.167 -14.297,73.167 -13.497,72.367 -13.497,71.467 -14.197,71.467 -14.229,71.499 -18.59,71.499 -19.09,70.999
  pour cut-out: -28.06,28.51 -32.9,28.51 -32.9,40.97 -30.6,40.97 -30.6,38.43 -28.06,38.43 -28.06,30.81
  pour cut-out: 22.572,48.508 25.772,48.508 25.772,47.437 24.368,46.033 24.368,45.422 23.993,45.422 22.572,46.842 22.572,47.808
  pour cut-out: 11.55,67.401 14.9,67.401 14.911,67.412 14.911,68.982 14.009,69.884 12.54,69.884 11.549,68.893
  pour cut-out: -0.256,66.893 5.015,66.893 5.149,67.027 5.149,68.754 3.519,70.384 2.758,70.384 1.003,68.63 -0.256,68.63
  pour cut-out: -0.256,72.9 0.976,72.9 1.936,71.94 1.936,70.86 0.623,69.547 -0.256,69.547
  region net PMODE0: -1.256,69.538 -0.556,69.538 -0.556,67.193 -1.256,67.193
  region net PMODE1: -1.256,72.378 -0.556,72.378 -0.556,70.084 -1.256,70.084
  region net PMODE2: -1.256,72.909 -1.256,75.157 -0.556,75.157 -0.556,72.909
  region net AGND: 25.23,41.988 25.23,40.556 24.579,39.905 23.754,39.905 23.683,39.976 23.683,40.441 24.23,40.988 24.23,41.988
  region net 3V3A: 25.715,41.98 25.715,40.69 24.675,39.65 23.4,39.65 23.275,39.525 23.275,38.8 23.4,38.675 25.95,38.675 26.735,39.46 26.735,41.98
  region net 3V3: -7.367,70.747 -7.367,72.717 -4.783,72.717 -4.06,73.44 -4.06,75.15 -1.963,75.15 -1.956,75.157 -1.956,74.257 -3.068,74.257 -3.2,74.125 -3.2,71.528 -2.656,70.984 -1.956,70.984 -1.956,68.638 -2.656,68.638 -4.175,68.638 -4.175,70.619 -4.793,71.238 -6.319,71.238 -6.809,70.747
  region net 5V: 22.872,48.808 22.872,51.376 23.599,52.103 25.128,52.103 28.075,55.05 29.9,55.05 30.325,54.625 30.325,53.675 29.5,52.85 28.625,52.85 27.075,51.3 25.775,51.3 25.472,50.997 25.472,48.808 24.772,48.808 24.772,50.543 24.565,50.75 23.825,50.75 23.572,50.497 23.572,48.808
  region net 3V3: 24.772,47.508 24.53,47.266 24.53,45.092 24.227,44.789 24.227,42.524 26.824,42.524 26.965,42.665 26.965,46.015 25.472,47.508
  region net NetDD6_4: 23.572,47.508 23.83,47.25 23.83,44.192 22.408,44.192 20.905,45.695 20.905,46.764 22.129,46.764 22.872,47.508
Layer 1:
  pour cut-out: -15.369,46.978 -15.369,47.673 -14.434,48.609 -14.434,60.45 -12.625,60.45 -11.872,59.697 -11.872,46.096
  pour cut-out: -13.369,53.437 -13.459,53.527 -13.459,66.541 -13.175,66.825 -12.06,66.825 -11.388,66.153 -12.679,64.862 -12.679,53.371
  pour cut-out: -12.679,52.148 -12.679,48.904 -11.15,47.375 -9.47,47.375 -5.482,43.387 -5.482,38.857 -6.86,37.479 -13.21,37.479 -15.344,39.614 -15.344,46.281 -13.392,48.233
Bottom Layer:
  pour cut-out: 14.227,73.944 11.655,71.371 11.54,71.487 14.064,74.01 14.327,74.01
  pour cut-out: 21.575,54.95 22.246,54.279 22.246,49.921 21.9,49.575 21.457,49.575 21.457,54.359 21.831,54.732
  pour cut-out: 32.71,63.358 33.1,63.358 33.919,62.539 33.919,34.1 34.777,34.1 34.777,66.012 33.487,66.012 32.65,65.175
  pour cut-out: -34.443,35.752 -32.91,35.752 -32.542,35.384 -32.542,33.906 -32.692,33.756 -33.715,33.756 -34.593,34.633
  pour cut-out: -10.018,52.621 -5.519,57.119 -6.147,57.747 -7.179,57.747 -11.448,53.478 -11.448,52.621
  pour cut-out: 32.725,50.3 28.391,50.3 26.554,52.137 26.554,54.254 27.51,55.21 31.901,55.21 33.257,53.854 33.257,53.717
  pour cut-out: 32.655,28.339 32.655,27.897 32.383,27.625 -9.3,27.625 -9.625,27.95 -9.625,28.269 -9.284,28.61 -5.316,28.61
  region net GND: 25.174,41.035 25.574,41.434 23.577,43.43 21.923,43.43 21.923,41.112 22,41.035
  pour cut-out: 26.032,51.577 27.692,49.918 30.849,49.918 30.849,43.54 30.206,42.897 29.448,42.897 25.34,47.005
  pour cut-out: 24.08,43.761 22.325,45.516 22.325,48.725 24.4,48.725 25.851,47.274 25.851,44.515

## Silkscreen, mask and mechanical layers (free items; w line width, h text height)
Top Overlay:
  text "A" at 28.225,90.475 h3
  text "GND" at 33.65,90.45 h3
  text "5V" at 38.75,90.45 h3
  text "B" at 32.025,90.425 h3
  text "L" at 22.083,90.351 h3
  text "L" at -28.9,90.325 h3
  text "L" at -11.792,90.325 h3
  text "L" at 5.045,90.325 h3
  text "H" at 18.608,90.276 h3
  text "H" at -32.375,90.25 h3
  text "H" at -15.267,90.25 h3
  text "H" at 1.57,90.25 h3
  text "GND" at 8.433,90.201 h3
  text "GND" at -42.55,90.175 h3
  text "GND" at -25.442,90.175 h3
  text "GND" at -8.605,90.175 h3
  text "12V" at 13.783,90.176 h3
  text "12V" at -37.2,90.15 h3
  text "12V" at -20.092,90.15 h3
  text "12V" at -3.255,90.15 h3
  text "CAN1" at -37.339,88.072 h3
  text "CAN1" at -20.041,87.901 h3
  text "CAN0" at -2.716,87.901 h3
  text "CAN0" at 13.764,87.901 h3
  text "RS-485" at 31.814,87.901 h3
  text "TP1" at 15.71,76.842 h3
  text "5V_EXT" at -13.298,48.752 h3 r90
  text "5V_CAN" at -10.671,48.752 h3 r90
  text "5V" at -8.552,48.752 h3 r90
  text "DUP" at -17.505,35.777 h3 r90
  text "IND" at -23.04,35.768 h3 r90
  text "SPD" at -14.857,35.738 h3 r90
  text "ALARM" at -20.192,35.719 h3 r90
Bottom Overlay:
  drawing of 16 lines, arcs and shapes, not listed
  text "EXU-NET-1.1" at 2.925,73.9 h3
Mechanical 1:
  lines w0.254: 42.618,21.589 72.193,21.589 72.193,27.019 42.618,27.019 42.618,21.589
  text "ProjectName: EXU-ETH-1.0" at 43.368,25.005 h2.5
  text "TimeStamp: .ModifiedDate .ModifiedTime" at 43.368,22.627 h2.5
Mechanical 4:
  lines w0.15: -44.5,85.5 -40,81 -40,29.352 -40,28.895 ccw(c-38.73,28.895) -38.73,27.625 38.73,27.625 ccw(c38.73,28.895) 40,28.895 40,29.925 40,81 44.5,85.5 44.5,98.527 44.5,100.802 ccw(c43.23,100.802) 43.23,102.072 -43.23,102.072 ccw(c-43.23,100.802) -44.5,100.802 -44.5,98.527 -44.5,85.5
Mechanical 13:
  lines w0.05: -40,27.642 40,27.642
